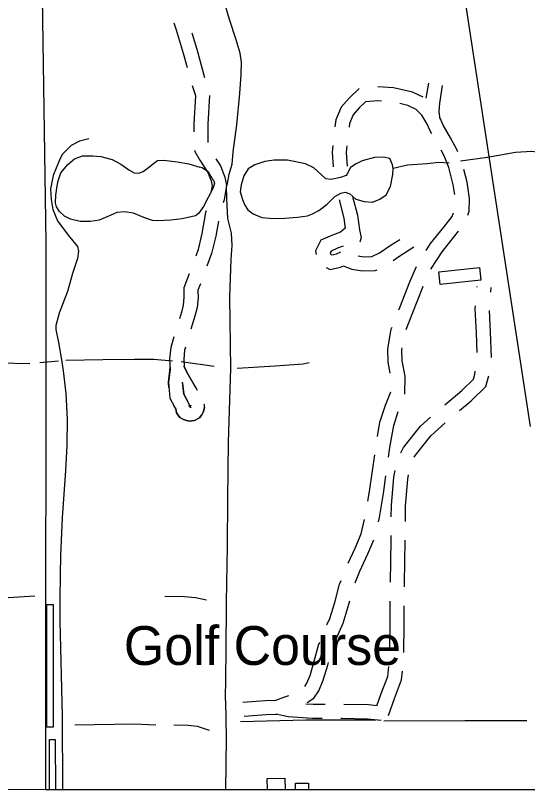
# Model space of a CAD drawing. Extents: x 3250478 to 3288318, y 788638 to 816472.
# Drawn here: x 3266413 to 3267506, y 794014 to 795675 of the extents above; entities that cross this region are included whole.
import ezdxf

# ---------------------------------------------------------------- set-up
doc = ezdxf.new("R2010")
doc.units = 0
for name, color, linetype in [('V-BLDG-OTLN', 7, 'Continuous'), ('V-GRID-FRAM', 7, 'Continuous'), ('V-ROAD-CNTR', 7, 'Continuous'), ('V-SITE-OTLN', 7, 'Continuous'), ('V-TOPO-GNAM-IDEN', 7, 'Continuous'), ('V-TOPO-SHOR', 7, 'Continuous')]:
    doc.layers.add(name, color=color, linetype=linetype)

msp = doc.modelspace()

# ---------------------------------------------------------------- linework, layer by layer
at = {"layer": 'V-BLDG-OTLN'}
for p, q in [((3266950.2, 794043.7), (3266988.2, 794044.4)), ((3266950.6, 794019.1), (3266950.2, 794043.7)), ((3266988.2, 794044.4), (3266988.6, 794019.1)), ((3267010.3, 794033.2), (3267038.2, 794033.6)), ((3267010.6, 794019.1), (3267010.3, 794033.2)), ((3267038.2, 794033.6), (3267038.5, 794019.1)), ((3266988.6, 794019.1), (3266950.6, 794019.1)), ((3267038.5, 794019.1), (3267010.6, 794019.1))]:
    msp.add_line(p, q, dxfattribs=at)
msp.add_lwpolyline([(3267403.5, 795135.9), (3267406.3, 795109.1), (3267319.8, 795099.9), (3267316.9, 795126.7)], close=True, dxfattribs=at)
at = {"layer": 'V-GRID-FRAM'}
msp.add_lwpolyline([(3254649.6, 812209.1), (3286070.1, 812200), (3286072.7, 794013.5), (3254636.4, 794022.7), (3254649.6, 812209.1)], dxfattribs=at)
at = {"layer": 'V-ROAD-CNTR'}
for p, q in [((3267398.5, 795094), (3267398.7, 795095.8)), ((3267427.8, 795083.7), (3267428.6, 795093.3))]:
    msp.add_line(p, q, dxfattribs=at)
for points in [[(3266751.1, 795659.5), (3266756, 795644.3), (3266770.8, 795594.8), (3266779.3, 795563.6)], [(3266789.2, 795638.2), (3266799.6, 795603), (3266816.4, 795542.1)], [(3266790, 795525.1), (3266795.3, 795508.5), (3266796.8, 795502.9), (3266793.7, 795443.3), (3266793.7, 795426.2)], [(3267146.9, 795518.8), (3267125.3, 795498.1), (3267108.3, 795479.1), (3267096.9, 795451.7), (3267094.7, 795437)], [(3267283.1, 795500.5), (3267260.5, 795510.9), (3267220.3, 795520.6), (3267186.6, 795522.2)], [(3267289.9, 795497.9), (3267295.1, 795530.3)], [(3267319.5, 795453.1), (3267317.5, 795468.9), (3267318.6, 795487.8), (3267324.7, 795525.5)], [(3266826.9, 795503.6), (3266823.7, 795442.5), (3266823.7, 795403.7)], [(3267194.1, 795491.8), (3267186.5, 795492.2), (3267160.4, 795490.2), (3267146.8, 795477.2), (3267134, 795462.9), (3267126, 795443.7), (3267125, 795436.3)], [(3267302, 795421.9), (3267299, 795427.1), (3267291.3, 795444.3), (3267280.8, 795462.2), (3267268.3, 795474.3), (3267250.6, 795482.4), (3267233.6, 795486.5)], [(3267357.2, 795383.6), (3267355.7, 795387.3), (3267341.6, 795413.2), (3267325.8, 795440.8), (3267319.3, 795455.1)], [(3266569, 795411.3), (3266549.5, 795406.4), (3266531.6, 795396.7), (3266512.4, 795377.9), (3266505.6, 795364.3), (3266492.9, 795332.8), (3266487.4, 795304), (3266488.4, 795281.7), (3266492.6, 795260.3), (3266502.6, 795235.7), (3266525.2, 795205.3), (3266544.8, 795180.9), (3266547.3, 795170.8), (3266544.9, 795155.7), (3266534.4, 795123.3), (3266523.3, 795084.6), (3266505.9, 795038.5), (3266499, 795012.1), (3266498.7, 795003.3), (3266504.4, 794975.4), (3266510.7, 794938.6), (3266514.4, 794914.8), (3266520.4, 794866.6), (3266523.1, 794811.6), (3266522.5, 794755.8), (3266519.6, 794702.3), (3266512.2, 794600.9), (3266508.9, 794519.9), (3266508, 794479.4), (3266507, 794425.4)], [(3266795.3, 795386.3), (3266795.7, 795384), (3266806, 795365.9), (3266823.4, 795339.5), (3266830.7, 795321.1), (3266832.5, 795311.1), (3266830.1, 795296.2)], [(3267090.3, 795397.2), (3267089, 795382.8), (3267090.8, 795351.2)], [(3267120.4, 795396.6), (3267119.1, 795382.3), (3267120.7, 795352.9)], [(3267350.8, 795292.1), (3267347.7, 795312.7), (3267337.9, 795350), (3267328.4, 795374.7), (3267321.7, 795387.1)], [(3266840.3, 795368.3), (3266850.2, 795353.4), (3266859.8, 795329.3), (3266862.9, 795311.3), (3266858.1, 795281), (3266856, 795274.1)], [(3267378.4, 795247.8), (3267381.9, 795256.6), (3267382.4, 795283.7), (3267377.2, 795318.8), (3267370.1, 795345.8)], [(3267132.7, 795288.2), (3267143.1, 795247.7), (3267147.6, 795216.6), (3267150.7, 795200.5), (3267147.7, 795190.6)], [(3267103.6, 795280.7), (3267113.6, 795241.8), (3267116.9, 795219.6)], [(3266819.8, 795257.6), (3266818.6, 795253.7), (3266810.8, 795208.9), (3266802.5, 795174.3), (3266797.4, 795160.4)], [(3267289.7, 795172.5), (3267299.3, 795187.4), (3267327.6, 795222.2), (3267345, 795245), (3267348.2, 795253.1)], [(3266845.9, 795235.5), (3266840.2, 795202.8), (3266831.3, 795165.7), (3266821.5, 795138.8)], [(3267117, 795220.3), (3267106.7, 795211.5), (3267089.4, 795205.2), (3267064.4, 795194.3), (3267053.3, 795171.5), (3267054.7, 795164.2)], [(3267300, 795132.8), (3267323.6, 795169.8), (3267351.2, 795203.7), (3267358.6, 795213.5)], [(3267144.3, 795161), (3267155.9, 795159.1), (3267173.8, 795159.4), (3267189.8, 795167.5), (3267215.2, 795184.4), (3267233.5, 795196.3)], [(3267112.8, 795181.8), (3267100.5, 795177.4), (3267086.5, 795171.2), (3267084.7, 795167.4), (3267085.2, 795164.6), (3267088.1, 795163.3), (3267097.9, 795165.5), (3267107.3, 795169.3)], [(3267219.5, 795151.2), (3267231.7, 795159.3), (3267263.5, 795180)], [(3267076.1, 795135.8), (3267084.9, 795131.8), (3267106.9, 795136.7), (3267114.1, 795139.6)], [(3267112.5, 795139.5), (3267130.8, 795132.7), (3267153.8, 795129.1), (3267181.1, 795129.5), (3267184.9, 795131.4)], [(3267231.7, 795045.8), (3267233.6, 795050.7), (3267254.9, 795105.7), (3267269.1, 795138.3)], [(3266783.5, 795122.9), (3266772.1, 795092.8), (3266772.3, 795072), (3266771, 795055.6), (3266767, 795040.6), (3266762.6, 795026.3)], [(3266807.4, 795101.4), (3266802.1, 795087.5), (3266802.4, 795070.9), (3266800.6, 795050.5), (3266795.9, 795032.4), (3266787.2, 795004.4)], [(3267247.2, 795003.3), (3267261.6, 795039.8), (3267282.6, 795094.2), (3267283.6, 795096.4)], [(3267398.6, 794954.3), (3267397, 794996.5), (3267394.7, 795047.6), (3267395.2, 795054.1)], [(3267429.1, 794944), (3267426.9, 794997.7), (3267424.9, 795043.9)], [(3267213.1, 794910), (3267208.5, 794933.6), (3267207.9, 794962.5), (3267215.3, 795004.2), (3267217.1, 795008.5)], [(3266751, 794988), (3266744.2, 794965.2), (3266741.8, 794940.5), (3266743.2, 794917.5)], [(3266775.8, 794966.1), (3266773.8, 794959.4), (3266771.9, 794939.9), (3266772.8, 794924), (3266781.1, 794907.1), (3266800.7, 794873.7)], [(3267244.4, 794865.2), (3267245, 794903.4), (3267238.4, 794936.8), (3267238, 794960.1), (3267238.7, 794964.4)], [(3266740.4, 794878.9), (3266739.3, 794891.1), (3266743.2, 794922)], [(3266797.5, 794879.1), (3266781.1, 794907.1), (3266772.3, 794925.1)], [(3266742.7, 794917.9), (3266739.3, 794891.1), (3266742.5, 794856.5), (3266751.5, 794839.6)], [(3267329.3, 794842.7), (3267365.6, 794873), (3267390.7, 794897.3), (3267393.7, 794908.2), (3267394.6, 794914.6)], [(3267361.1, 794830.1), (3267385.7, 794850.7), (3267417.4, 794881.4), (3267423.1, 794902), (3267423.5, 794904.4)], [(3266775.4, 794857.5), (3266778.9, 794851.6), (3266787, 794835.8), (3266786.5, 794837.7), (3266786.5, 794840.4), (3266786.8, 794841.7), (3266785.5, 794838), (3266785.1, 794837.1), (3266786, 794838.2), (3266785, 794837.6), (3266786.1, 794837.8), (3266786.5, 794837.8), (3266785.7, 794838), (3266783.5, 794838.7), (3266784.2, 794838.3), (3266784.4, 794838), (3266783.3, 794843.8), (3266771.8, 794865.3), (3266769.4, 794890.6), (3266769.5, 794891.2)], [(3266769.6, 794889.1), (3266771.8, 794865.3), (3266782.2, 794845.8)], [(3267186, 794774.8), (3267191.1, 794805.5), (3267202.7, 794841.8), (3267214.5, 794870.1), (3267214.5, 794870.2)], [(3266816.5, 794837.5), (3266816.5, 794837.2), (3266815.7, 794833.4), (3266813.4, 794826.9), (3266810.8, 794821), (3266805.3, 794814.6), (3266794.6, 794808.7), (3266789.2, 794807.9), (3266784.4, 794807.6), (3266778, 794808.9), (3266771.1, 794811.2), (3266763.8, 794815.4), (3266756.3, 794825.5), (3266754.7, 794833.6), (3266750.7, 794841.1)], [(3266754.3, 794835.8), (3266756.3, 794825.5), (3266763.8, 794815.4), (3266771.1, 794811.2), (3266778, 794808.9), (3266784.4, 794807.6), (3266789.2, 794807.9), (3266794.6, 794808.7), (3266805.3, 794814.6), (3266810.8, 794821), (3266813.4, 794826.9), (3266815.7, 794833.4), (3266816.5, 794837.2), (3266816.5, 794841.6), (3266815.9, 794843.7)], [(3267209.4, 794730.4), (3267212.4, 794751.1), (3267220.4, 794798.4), (3267229.8, 794828)], [(3267235.6, 794740), (3267241.4, 794751.4), (3267277.9, 794797), (3267299.3, 794816.3)], [(3267264.2, 794730.2), (3267266.7, 794735.1), (3267299.8, 794776.4), (3267330.6, 794804.2)], [(3267165.4, 794636.4), (3267168.7, 794657.4), (3267174.8, 794701.4), (3267179.8, 794735.3)], [(3267187.9, 794592.1), (3267190.1, 794601.2), (3267198.4, 794653), (3267203.6, 794690.8)], [(3267215.3, 794602.8), (3267215.4, 794626.9), (3267220.5, 794687.7), (3267223.4, 794702.3)], [(3267245.3, 794592.9), (3267245.4, 794625.6), (3267250.3, 794683.6), (3267252, 794692.5)], [(3267122.8, 794503.9), (3267137.8, 794536.2), (3267150.8, 794566.9), (3267158.2, 794597.1)], [(3267213.3, 794462.9), (3267215.1, 794552.7), (3267215.1, 794562.8)], [(3267138.1, 794461.8), (3267147.9, 794486.7), (3267165.3, 794524), (3267177.8, 794553.5)], [(3267243.2, 794452.9), (3267243.2, 794461.3), (3267245.1, 794552.4), (3267245.1, 794552.9)], [(3267077.9, 794371.7), (3267083.9, 794385.8), (3267094.5, 794419.7), (3267104.9, 794459.2), (3267107.9, 794466.8)], [(3266507, 794425.4), (3266507.5, 794379.9), (3266512.4, 794177.6), (3266512.6, 794019.2)], [(3267092.9, 794329.7), (3267098.5, 794343.4), (3267112.1, 794375.5), (3267123.3, 794411.4), (3267126.5, 794423.5)], [(3267212.3, 794322.9), (3267212.7, 794373.6), (3267213, 794422.9)], [(3267242.2, 794312.9), (3267242.7, 794373.4), (3267243, 794412.9)], [(3267030.7, 794240.4), (3267034.2, 794245.5), (3267041.7, 794263.4), (3267050.6, 794294.2), (3267060, 794328.7), (3267062.5, 794334.8)], [(3267035.7, 794206.1), (3267049.6, 794215), (3267060.7, 794231.1), (3267070, 794253.4), (3267079.5, 794286), (3267081, 794291.6)], [(3267184.7, 794198.8), (3267193.6, 794224.8), (3267207.6, 794261.8), (3267210.2, 794283)], [(3267209.3, 794178.1), (3267221.8, 794214.6), (3267236.9, 794254.6), (3267239.2, 794273.1)], [(3266898.4, 794206.3), (3266945.9, 794210.2), (3266968.7, 794211.2), (3266988, 794218), (3266996.5, 794221)], [(3267032.5, 794203.2), (3267048.2, 794202.1), (3267074, 794202.2)], [(3267114, 794202.4), (3267166.5, 794201.3), (3267185.2, 794199.2)], [(3266900.9, 794176.4), (3266947.8, 794180.3), (3266970.5, 794181.2)], [(3266968.4, 794181.6), (3266995.3, 794175.8), (3267047.2, 794172.1), (3267067.6, 794172.2)], [(3267107.6, 794172.4), (3267110.3, 794172.5), (3267164.5, 794171.3), (3267193.4, 794168)]]:
    msp.add_lwpolyline(points, dxfattribs=at)
at = {"layer": 'V-SITE-OTLN'}
for p, q in [((3266478.1, 795189.6), (3266452.1, 796922.9)), ((3267295.1, 796213.4), (3267511.7, 794795.9)), ((3266477.6, 794019.2), (3266478.1, 795189.6)), ((3267601.2, 794018.9), (3266477.6, 794019.2))]:
    msp.add_line(p, q, dxfattribs=at)
at = {"layer": 'V-TOPO-SHOR'}
for p, q in [((3266464.2, 794933.2), (3266504.6, 794936.4)), ((3266766.3, 794935.3), (3266837.1, 794925.3))]:
    msp.add_line(p, q, dxfattribs=at)
for points in [[(3266861.4, 794210.4), (3266862.2, 794312.7), (3266862.9, 794420.4), (3266865.3, 794540), (3266866, 794641.6), (3266867.3, 794762.7), (3266872.2, 794920.4), (3266870.7, 795072.5), (3266873.2, 795153.5), (3266875.2, 795183.3), (3266873.8, 795209.7), (3266866.4, 795240.9), (3266863.9, 795283.1), (3266863.5, 795309.1), (3266865.1, 795315.9), (3266869.3, 795335.7), (3266875.5, 795357.4), (3266877.8, 795383.7), (3266885.2, 795441.2), (3266891.9, 795508.3), (3266894.4, 795548.9), (3266895.1, 795575.4), (3266892.2, 795594.5), (3266884, 795622.8), (3266869.5, 795666.7), (3266857.7, 795707.6)], [(3266835.3, 795322.9), (3266837.7, 795316.3), (3266834.7, 795306.8), (3266813.9, 795266.3), (3266803.4, 795251.8), (3266797.3, 795246.8), (3266768.4, 795240), (3266744, 795237.3), (3266716.4, 795235.8), (3266705.2, 795236.9), (3266686.6, 795243.1), (3266664.4, 795252.3), (3266645.3, 795255), (3266628.8, 795253.9), (3266609.6, 795245), (3266591, 795237.6), (3266573, 795234.5), (3266551, 795234.4), (3266529.9, 795239.2), (3266517.5, 795246), (3266506.4, 795256.2), (3266500.4, 795265.8), (3266498.2, 795274.7), (3266498.4, 795291.1), (3266501.9, 795311.1), (3266503.5, 795321.4), (3266509.6, 795338.8), (3266524.4, 795356.4), (3266538.5, 795368.8), (3266555.8, 795375), (3266577.7, 795375.1), (3266594.5, 795373.4), (3266619.1, 795367.1), (3266637.4, 795357), (3266654.6, 795344.7), (3266666.2, 795338.7), (3266676.2, 795337.6), (3266685.3, 795341.2), (3266696.9, 795350), (3266704.8, 795356.6), (3266716.2, 795364.9), (3266729.6, 795365.6), (3266758.2, 795362.4), (3266782.5, 795357.5), (3266806.2, 795350.8)], [(3267219.5, 795348), (3267218, 795355.7), (3267212.2, 795369), (3267198.9, 795372.4), (3267179.2, 795371), (3267153.3, 795364), (3267140.1, 795357.5), (3267128.4, 795349.8), (3267120.1, 795335), (3267119.2, 795332.7), (3267106.5, 795328.5), (3267086.3, 795324.6), (3267075.6, 795325.6), (3267049.7, 795348.9), (3267031.9, 795357.7), (3266993.3, 795365.8), (3266964.9, 795365.5), (3266945.3, 795363), (3266923.7, 795355.7), (3266909.4, 795347.2), (3266900.4, 795332), (3266894.4, 795312.9), (3266892.8, 795298.1), (3266897.5, 795281.8), (3266902.6, 795269.6), (3266908.5, 795259.2), (3266920.2, 795251.1), (3266938.4, 795243.3), (3266963.2, 795240.8), (3266988.2, 795241.9), (3267015.1, 795244.1), (3267036.2, 795246.4), (3267047.3, 795250.6), (3267060.7, 795258.1), (3267078, 795271.6), (3267094.4, 795288), (3267107.7, 795295.4), (3267116.8, 795297.2), (3267126.8, 795293.3), (3267139.5, 795282.4), (3267157, 795277.2), (3267175, 795275.7), (3267191, 795282.2), (3267204.3, 795291.8), (3267213.8, 795309.2), (3267218.4, 795335.1), (3267219.5, 795348)], [(3267742.5, 795372.2), (3267697.8, 795376.7), (3267631.5, 795378.5), (3267557.6, 795378.8), (3267515.4, 795384), (3267480.6, 795382.1), (3267420.7, 795371), (3267363.2, 795363.5)], [(3267338.8, 795359.2), (3267317, 795360.5), (3267292, 795358.1), (3267249.6, 795354.8), (3267219.5, 795348)], [(3266835.3, 795322.9), (3266833.7, 795325.7), (3266831.9, 795328.3), (3266830, 795331.2), (3266827.1, 795336.6), (3266825.2, 795339.1), (3266822.7, 795341.5), (3266819.6, 795343.8), (3266816.5, 795345.7), (3266811.1, 795349.2), (3266806.2, 795350.8)], [(3266190.4, 794938.6), (3266308.4, 794935.3), (3266378, 794932.5), (3266443.1, 794931)], [(3266520.4, 794938.1), (3266599.3, 794939.5), (3266667, 794940.4), (3266707.8, 794940.4), (3266747.6, 794936.5)], [(3266885.8, 794920.8), (3266967.3, 794925.6), (3267027, 794930.4), (3267039.9, 794932.8)], [(3266103.9, 794420.1), (3266177.1, 794424.8), (3266244.2, 794434.5), (3266310.9, 794433.2), (3266346.3, 794427.1), (3266385.6, 794429.7), (3266454.2, 794433.7)], [(3266731.7, 794433.6), (3266773.8, 794432.5), (3266796.9, 794430.2), (3266820.7, 794425.3)], [(3266479.8, 794153), (3266479.8, 794415.7), (3266492.8, 794415.7), (3266492.8, 794153), (3266479.8, 794153)], [(3266861.4, 794210.4), (3266862.8, 794129.4), (3266861.2, 794019.1)], [(3266539.6, 794158.4), (3266665.7, 794160.3), (3266712.3, 794157.9)], [(3266750.7, 794158.4), (3266781.1, 794157.6), (3266800.7, 794155.5), (3266825.9, 794146.9)], [(3267182, 794167.9), (3267032.4, 794168.1), (3266892.9, 794164.5)], [(3267199.2, 794166.6), (3267372.4, 794167.1), (3267504.9, 794167.7)], [(3266485.4, 794019.2), (3266485, 794127.1), (3266497.5, 794127.1), (3266497.8, 794019.2)]]:
    msp.add_lwpolyline(points, dxfattribs=at)

# ---------------------------------------------------------------- texts
at = {"layer": 'V-TOPO-GNAM-IDEN'}
msp.add_text('Golf Course', height=83, dxfattribs=at).set_placement((3266644, 794286.2))

doc.saveas('drawing.dxf')
